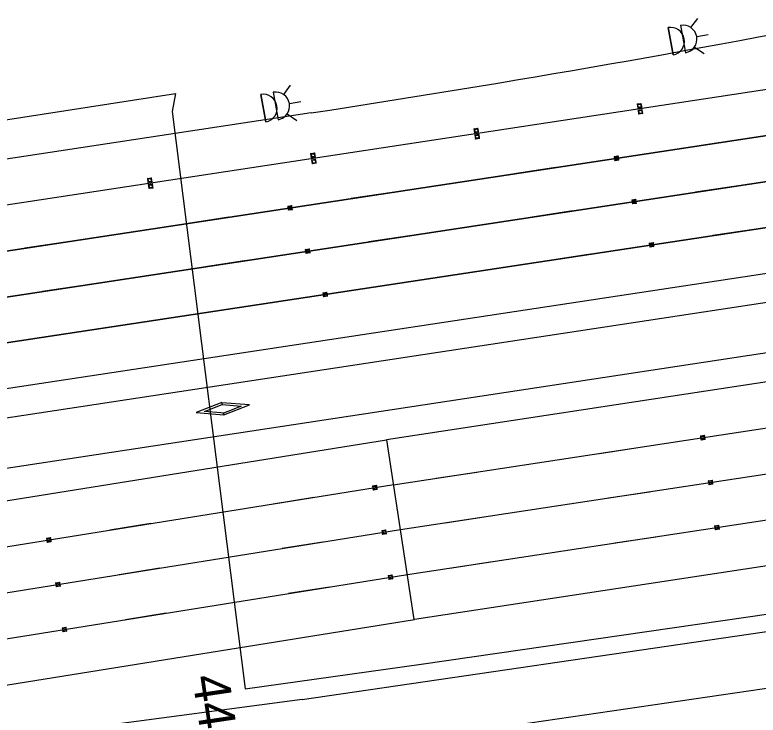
# Model space of a CAD drawing. Extents: x 2471014 to 2497726, y 6959577 to 6980268.
# Drawn here: x 2480648.2 to 2480828.3, y 6967099.5 to 6967269 of the extents above; entities that cross this region are included whole.
import ezdxf

# ---------------------------------------------------------------- set-up
doc = ezdxf.new("R2010")
doc.units = 0
for name, color, linetype in [('1', 7, 'Continuous'), ('13', 7, 'Continuous'), ('15', 7, 'Continuous'), ('18', 7, 'Continuous'), ('23', 7, 'Continuous'), ('25', 7, 'Continuous'), ('5', 7, 'Continuous'), ('C-COMM-IDEN', 7, 'Continuous'), ('PMK_Pav_Mark_Wht_Number', 7, 'Continuous'), ('PMK_Pav_Mark_Wht_Symb', 7, 'Continuous'), ('S-BRDG-BENT', 7, 'Continuous'), ('V7_25', 7, 'Continuous'), ('V7_50', 7, 'Continuous')]:
    doc.layers.add(name, color=color, linetype=linetype)

msp = doc.modelspace()

# ---------------------------------------------------------------- linework, layer by layer
at = {"layer": '1'}
for p, q in [((2480818.71, 6967238.03), (2480808.82, 6967236.53)), ((2480779.16, 6967232.03), (2480769.27, 6967230.53)), ((2480822.95, 6967227.55), (2480813.07, 6967226.05)), ((2480739.61, 6967226.02), (2480729.73, 6967224.52)), ((2480783.41, 6967221.55), (2480773.52, 6967220.04)), ((2480700.07, 6967220.02), (2480690.18, 6967218.52)), ((2480827.2, 6967217.07), (2480817.31, 6967215.57)), ((2480743.86, 6967215.54), (2480733.97, 6967214.04)), ((2480660.52, 6967214.01), (2480650.63, 6967212.51)), ((2480704.31, 6967209.54), (2480694.43, 6967208.03)), ((2480787.65, 6967211.06), (2480777.76, 6967209.56)), ((2480748.1, 6967205.06), (2480738.22, 6967203.56)), ((2480664.77, 6967203.53), (2480654.88, 6967202.03)), ((2480708.56, 6967199.05), (2480698.67, 6967197.55)), ((2480669.01, 6967193.05), (2480659.12, 6967191.55)), ((2480789.81, 6967162.84), (2480799.7, 6967164.34)), ((2480750.27, 6967156.84), (2480760.15, 6967158.34)), ((2480792.04, 6967152.05), (2480801.93, 6967153.56)), ((2480720.63, 6967152.17), (2480710.76, 6967150.59)), ((2480752.5, 6967146.05), (2480762.38, 6967147.55)), ((2480681.14, 6967145.84), (2480671.26, 6967144.25)), ((2480722.86, 6967141.39), (2480712.99, 6967139.81)), ((2480793.59, 6967141.16), (2480803.48, 6967142.67)), ((2480754.05, 6967135.16), (2480763.93, 6967136.66)), ((2480683.37, 6967135.05), (2480673.49, 6967133.47)), ((2480724.41, 6967130.5), (2480714.54, 6967128.91)), ((2480684.91, 6967124.16), (2480675.04, 6967122.58))]:
    msp.add_line(p, q, dxfattribs=at)
at = {"layer": '13'}
for p, q in [((2481763.47, 6967348.11), (2480328.46, 6967130.21)), ((2481593.94, 6967296.07), (2480738.25, 6967166.14)), ((2480338.75, 6967102.06), (2480738.25, 6967166.14))]:
    msp.add_line(p, q, dxfattribs=at)
at = {"layer": '15'}
for p, q in [((2480717.84, 6967103.25), (2481462.38, 6967212.06)), ((2480719.04, 6967089.77), (2481463.87, 6967198.71))]:
    msp.add_line(p, q, dxfattribs=at)
msp.add_lwpolyline([(2480717.84, 6967103.25), (2480607.69, 6967088.69), (2480530.66, 6967079.46)], dxfattribs=at)
at = {"layer": '18'}
for p, q in [((2481764.52, 6967341.19), (2480329.51, 6967123.29)), ((2481592.89, 6967302.99), (2480331.31, 6967111.43)), ((2481600.55, 6967252.57), (2480745.04, 6967122.66)), ((2480719.99, 6967245.29), (2480411.94, 6967198.52))]:
    msp.add_line(p, q, dxfattribs=at)
msp.add_arc((2480242.59, 6970389.25), 3180, 278.63432, 283.91609, dxfattribs=at)
at = {"layer": '23'}
for p, q in [((2480798.96, 6967247.44), (2480799.96, 6967247.59)), ((2480799.15, 6967247.29), (2480798.96, 6967247.44)), ((2480798.96, 6967247.44), (2480799.11, 6967246.44)), ((2480799.23, 6967246.76), (2480799.15, 6967247.29)), ((2480799.96, 6967247.59), (2480799.82, 6967247.39)), ((2480799.82, 6967247.39), (2480799.92, 6967246.72)), ((2480800.07, 6967246.86), (2480799.96, 6967247.59)), ((2480799.11, 6967246.44), (2480799.25, 6967246.62)), ((2480800.11, 6967246.59), (2480799.11, 6967246.44)), ((2480799.18, 6967245.96), (2480800.19, 6967246.11)), ((2480799.38, 6967245.81), (2480799.18, 6967245.96)), ((2480799.18, 6967245.96), (2480799.33, 6967244.95)), ((2480799.25, 6967246.62), (2480799.23, 6967246.76)), ((2480799.46, 6967245.28), (2480799.38, 6967245.81)), ((2480799.92, 6967246.72), (2480800.11, 6967246.59)), ((2480800.19, 6967246.11), (2480800.05, 6967245.91)), ((2480800.05, 6967245.91), (2480800.15, 6967245.24)), ((2480800.11, 6967246.59), (2480800.07, 6967246.86)), ((2480800.3, 6967245.37), (2480800.19, 6967246.11)), ((2480800.34, 6967245.11), (2480800.3, 6967245.37)), ((2480799.33, 6967244.95), (2480799.48, 6967245.14)), ((2480800.34, 6967245.11), (2480799.33, 6967244.95)), ((2480799.48, 6967245.14), (2480799.46, 6967245.28)), ((2480800.15, 6967245.24), (2480800.34, 6967245.11)), ((2480759.41, 6967241.44), (2480760.41, 6967241.59)), ((2480759.61, 6967241.29), (2480759.41, 6967241.44)), ((2480759.41, 6967241.44), (2480759.56, 6967240.43)), ((2480759.56, 6967240.43), (2480759.71, 6967240.62)), ((2480760.57, 6967240.59), (2480759.56, 6967240.43)), ((2480759.69, 6967240.76), (2480759.61, 6967241.29)), ((2480759.64, 6967239.95), (2480760.64, 6967240.1)), ((2480759.83, 6967239.8), (2480759.64, 6967239.95)), ((2480759.64, 6967239.95), (2480759.79, 6967238.95)), ((2480759.71, 6967240.62), (2480759.69, 6967240.76)), ((2480760.41, 6967241.59), (2480760.28, 6967241.39)), ((2480760.28, 6967241.39), (2480760.38, 6967240.72)), ((2480760.38, 6967240.72), (2480760.57, 6967240.59)), ((2480760.53, 6967240.85), (2480760.41, 6967241.59)), ((2480760.64, 6967240.1), (2480760.5, 6967239.9)), ((2480760.57, 6967240.59), (2480760.53, 6967240.85)), ((2480760.75, 6967239.37), (2480760.64, 6967240.1)), ((2480759.79, 6967238.95), (2480759.93, 6967239.13)), ((2480760.79, 6967239.1), (2480759.79, 6967238.95)), ((2480759.91, 6967239.27), (2480759.83, 6967239.8)), ((2480759.93, 6967239.13), (2480759.91, 6967239.27)), ((2480760.5, 6967239.9), (2480760.6, 6967239.23)), ((2480760.6, 6967239.23), (2480760.79, 6967239.1)), ((2480760.79, 6967239.1), (2480760.75, 6967239.37)), ((2480719.87, 6967235.43), (2480720.87, 6967235.58)), ((2480720.06, 6967235.28), (2480719.87, 6967235.43)), ((2480719.87, 6967235.43), (2480720.02, 6967234.43)), ((2480720.02, 6967234.43), (2480720.16, 6967234.61)), ((2480721.02, 6967234.58), (2480720.02, 6967234.43)), ((2480720.14, 6967234.75), (2480720.06, 6967235.28)), ((2480720.16, 6967234.61), (2480720.14, 6967234.75)), ((2480720.87, 6967235.58), (2480720.73, 6967235.38)), ((2480720.73, 6967235.38), (2480720.83, 6967234.71)), ((2480720.83, 6967234.71), (2480721.02, 6967234.58)), ((2480720.98, 6967234.85), (2480720.87, 6967235.58)), ((2480721.02, 6967234.58), (2480720.98, 6967234.85)), ((2480793.41, 6967234.71), (2480794.41, 6967234.87)), ((2480793.61, 6967234.56), (2480793.41, 6967234.71)), ((2480793.41, 6967234.71), (2480793.56, 6967233.71)), ((2480793.69, 6967234.03), (2480793.61, 6967234.56)), ((2480794.41, 6967234.87), (2480794.28, 6967234.66)), ((2480794.28, 6967234.66), (2480794.38, 6967234)), ((2480794.53, 6967234.13), (2480794.41, 6967234.87)), ((2480720.09, 6967233.95), (2480721.09, 6967234.1)), ((2480720.28, 6967233.8), (2480720.09, 6967233.95)), ((2480720.09, 6967233.95), (2480720.24, 6967232.94)), ((2480720.24, 6967232.94), (2480720.39, 6967233.13)), ((2480721.25, 6967233.1), (2480720.24, 6967232.94)), ((2480720.36, 6967233.27), (2480720.28, 6967233.8)), ((2480720.39, 6967233.13), (2480720.36, 6967233.27)), ((2480721.09, 6967234.1), (2480720.95, 6967233.9)), ((2480720.95, 6967233.9), (2480721.06, 6967233.23)), ((2480721.06, 6967233.23), (2480721.25, 6967233.1)), ((2480721.21, 6967233.36), (2480721.09, 6967234.1)), ((2480721.25, 6967233.1), (2480721.21, 6967233.36)), ((2480793.56, 6967233.71), (2480793.71, 6967233.89)), ((2480794.57, 6967233.86), (2480793.56, 6967233.71)), ((2480793.71, 6967233.89), (2480793.69, 6967234.03)), ((2480794.38, 6967234), (2480794.57, 6967233.86)), ((2480794.57, 6967233.86), (2480794.53, 6967234.13)), ((2480680.32, 6967229.43), (2480681.32, 6967229.58)), ((2480680.51, 6967229.28), (2480680.32, 6967229.43)), ((2480680.32, 6967229.43), (2480680.47, 6967228.42)), ((2480680.59, 6967228.75), (2480680.51, 6967229.28)), ((2480681.32, 6967229.58), (2480681.18, 6967229.38)), ((2480681.18, 6967229.38), (2480681.28, 6967228.71)), ((2480681.43, 6967228.84), (2480681.32, 6967229.58)), ((2480680.47, 6967228.42), (2480680.61, 6967228.61)), ((2480681.47, 6967228.58), (2480680.47, 6967228.42)), ((2480680.54, 6967227.94), (2480681.55, 6967228.09)), ((2480680.74, 6967227.79), (2480680.54, 6967227.94)), ((2480680.54, 6967227.94), (2480680.69, 6967226.94)), ((2480680.61, 6967228.61), (2480680.59, 6967228.75)), ((2480680.82, 6967227.26), (2480680.74, 6967227.79)), ((2480681.28, 6967228.71), (2480681.47, 6967228.58)), ((2480681.55, 6967228.09), (2480681.41, 6967227.89)), ((2480681.41, 6967227.89), (2480681.51, 6967227.22)), ((2480681.47, 6967228.58), (2480681.43, 6967228.84)), ((2480681.66, 6967227.36), (2480681.55, 6967228.09)), ((2480681.7, 6967227.09), (2480681.66, 6967227.36)), ((2480680.69, 6967226.94), (2480680.84, 6967227.12)), ((2480681.7, 6967227.09), (2480680.69, 6967226.94)), ((2480680.84, 6967227.12), (2480680.82, 6967227.26)), ((2480681.51, 6967227.22), (2480681.7, 6967227.09)), ((2480797.66, 6967224.23), (2480798.66, 6967224.38)), ((2480797.85, 6967224.08), (2480797.66, 6967224.23)), ((2480797.66, 6967224.23), (2480797.81, 6967223.23)), ((2480797.93, 6967223.55), (2480797.85, 6967224.08)), ((2480798.66, 6967224.38), (2480798.52, 6967224.18)), ((2480798.52, 6967224.18), (2480798.62, 6967223.51)), ((2480798.77, 6967223.65), (2480798.66, 6967224.38)), ((2480714.32, 6967222.7), (2480715.32, 6967222.85)), ((2480714.51, 6967222.55), (2480714.32, 6967222.7)), ((2480714.32, 6967222.7), (2480714.47, 6967221.7)), ((2480714.59, 6967222.02), (2480714.51, 6967222.55)), ((2480714.62, 6967221.88), (2480714.59, 6967222.02)), ((2480715.32, 6967222.85), (2480715.18, 6967222.65)), ((2480715.18, 6967222.65), (2480715.28, 6967221.99)), ((2480715.28, 6967221.99), (2480715.47, 6967221.85)), ((2480715.43, 6967222.12), (2480715.32, 6967222.85)), ((2480715.47, 6967221.85), (2480715.43, 6967222.12)), ((2480797.81, 6967223.23), (2480797.95, 6967223.41)), ((2480798.81, 6967223.38), (2480797.81, 6967223.23)), ((2480797.95, 6967223.41), (2480797.93, 6967223.55)), ((2480798.62, 6967223.51), (2480798.81, 6967223.38)), ((2480798.81, 6967223.38), (2480798.77, 6967223.65)), ((2480714.47, 6967221.7), (2480714.62, 6967221.88)), ((2480715.47, 6967221.85), (2480714.47, 6967221.7)), ((2480801.9, 6967213.75), (2480802.9, 6967213.9)), ((2480802.1, 6967213.6), (2480801.9, 6967213.75)), ((2480801.9, 6967213.75), (2480802.05, 6967212.75)), ((2480802.05, 6967212.75), (2480802.2, 6967212.93)), ((2480802.18, 6967213.07), (2480802.1, 6967213.6)), ((2480802.2, 6967212.93), (2480802.18, 6967213.07)), ((2480802.9, 6967213.9), (2480802.76, 6967213.7)), ((2480802.76, 6967213.7), (2480802.87, 6967213.03)), ((2480802.87, 6967213.03), (2480803.05, 6967212.9)), ((2480803.01, 6967213.17), (2480802.9, 6967213.9)), ((2480803.05, 6967212.9), (2480803.01, 6967213.17)), ((2480718.56, 6967212.22), (2480719.57, 6967212.37)), ((2480718.76, 6967212.07), (2480718.56, 6967212.22)), ((2480718.56, 6967212.22), (2480718.71, 6967211.22)), ((2480718.71, 6967211.22), (2480718.86, 6967211.4)), ((2480719.72, 6967211.37), (2480718.71, 6967211.22)), ((2480718.84, 6967211.54), (2480718.76, 6967212.07)), ((2480718.86, 6967211.4), (2480718.84, 6967211.54)), ((2480719.57, 6967212.37), (2480719.43, 6967212.17)), ((2480719.43, 6967212.17), (2480719.53, 6967211.5)), ((2480719.53, 6967211.5), (2480719.72, 6967211.37)), ((2480719.68, 6967211.64), (2480719.57, 6967212.37)), ((2480719.72, 6967211.37), (2480719.68, 6967211.64)), ((2480803.05, 6967212.9), (2480802.05, 6967212.75)), ((2480722.81, 6967201.74), (2480723.81, 6967201.89)), ((2480723, 6967201.59), (2480722.81, 6967201.74)), ((2480722.81, 6967201.74), (2480722.96, 6967200.74)), ((2480722.96, 6967200.74), (2480723.1, 6967200.92)), ((2480723.96, 6967200.89), (2480722.96, 6967200.74)), ((2480723.08, 6967201.06), (2480723, 6967201.59)), ((2480723.1, 6967200.92), (2480723.08, 6967201.06)), ((2480723.81, 6967201.89), (2480723.67, 6967201.69)), ((2480723.67, 6967201.69), (2480723.77, 6967201.02)), ((2480723.77, 6967201.02), (2480723.96, 6967200.89)), ((2480723.92, 6967201.16), (2480723.81, 6967201.89)), ((2480723.96, 6967200.89), (2480723.92, 6967201.16)), ((2480814.31, 6967167.06), (2480815.31, 6967167.22)), ((2480814.49, 6967166.93), (2480814.31, 6967167.06)), ((2480814.31, 6967167.06), (2480814.35, 6967166.8)), ((2480814.35, 6967166.8), (2480814.46, 6967166.06)), ((2480814.46, 6967166.06), (2480814.6, 6967166.26)), ((2480815.46, 6967166.21), (2480814.46, 6967166.06)), ((2480814.6, 6967166.26), (2480814.49, 6967166.93)), ((2480815.31, 6967167.22), (2480815.16, 6967167.03)), ((2480815.16, 6967167.03), (2480815.18, 6967166.89)), ((2480815.18, 6967166.89), (2480815.26, 6967166.36)), ((2480815.26, 6967166.36), (2480815.46, 6967166.21)), ((2480815.46, 6967166.21), (2480815.31, 6967167.22)), ((2480816.19, 6967156.22), (2480817.19, 6967156.38)), ((2480816.38, 6967156.09), (2480816.19, 6967156.22)), ((2480816.19, 6967156.22), (2480816.23, 6967155.96)), ((2480816.23, 6967155.96), (2480816.34, 6967155.22)), ((2480816.34, 6967155.22), (2480816.48, 6967155.42)), ((2480817.34, 6967155.37), (2480816.34, 6967155.22)), ((2480816.48, 6967155.42), (2480816.38, 6967156.09)), ((2480817.19, 6967156.38), (2480817.04, 6967156.19)), ((2480817.04, 6967156.19), (2480817.07, 6967156.05)), ((2480817.07, 6967156.05), (2480817.15, 6967155.52)), ((2480817.15, 6967155.52), (2480817.34, 6967155.37)), ((2480817.34, 6967155.37), (2480817.19, 6967156.38)), ((2480734.86, 6967154.98), (2480735.86, 6967155.14)), ((2480735.06, 6967154.83), (2480734.86, 6967154.98)), ((2480734.86, 6967154.98), (2480735.02, 6967153.98)), ((2480735.02, 6967153.98), (2480735.16, 6967154.16)), ((2480736.02, 6967154.14), (2480735.02, 6967153.98)), ((2480735.14, 6967154.3), (2480735.06, 6967154.83)), ((2480735.16, 6967154.16), (2480735.14, 6967154.3)), ((2480735.86, 6967155.14), (2480735.72, 6967154.94)), ((2480735.72, 6967154.94), (2480735.83, 6967154.27)), ((2480735.83, 6967154.27), (2480736.02, 6967154.14)), ((2480735.98, 6967154.4), (2480735.86, 6967155.14)), ((2480736.02, 6967154.14), (2480735.98, 6967154.4)), ((2480817.73, 6967145.33), (2480818.74, 6967145.48)), ((2480817.92, 6967145.2), (2480817.73, 6967145.33)), ((2480817.73, 6967145.33), (2480817.77, 6967145.07)), ((2480817.77, 6967145.07), (2480817.89, 6967144.33)), ((2480817.89, 6967144.33), (2480818.02, 6967144.53)), ((2480818.02, 6967144.53), (2480817.92, 6967145.2)), ((2480818.74, 6967145.48), (2480818.59, 6967145.3)), ((2480818.59, 6967145.3), (2480818.61, 6967145.16)), ((2480818.61, 6967145.16), (2480818.69, 6967144.63)), ((2480818.69, 6967144.63), (2480818.89, 6967144.48)), ((2480818.89, 6967144.48), (2480818.74, 6967145.48)), ((2480737.09, 6967144.19), (2480738.09, 6967144.35)), ((2480737.29, 6967144.05), (2480737.09, 6967144.19)), ((2480737.09, 6967144.19), (2480737.25, 6967143.19)), ((2480737.25, 6967143.19), (2480737.39, 6967143.38)), ((2480738.25, 6967143.35), (2480737.25, 6967143.19)), ((2480737.37, 6967143.52), (2480737.29, 6967144.05)), ((2480737.39, 6967143.38), (2480737.37, 6967143.52)), ((2480738.09, 6967144.35), (2480737.95, 6967144.15)), ((2480737.95, 6967144.15), (2480738.06, 6967143.49)), ((2480738.06, 6967143.49), (2480738.25, 6967143.35)), ((2480738.21, 6967143.62), (2480738.09, 6967144.35)), ((2480738.25, 6967143.35), (2480738.21, 6967143.62)), ((2480818.89, 6967144.48), (2480817.89, 6967144.33)), ((2480655.87, 6967142.31), (2480656.87, 6967142.47)), ((2480656.06, 6967142.16), (2480655.87, 6967142.31)), ((2480655.87, 6967142.31), (2480656.03, 6967141.31)), ((2480656.03, 6967141.31), (2480656.17, 6967141.49)), ((2480657.03, 6967141.47), (2480656.03, 6967141.31)), ((2480656.15, 6967141.63), (2480656.06, 6967142.16)), ((2480656.17, 6967141.49), (2480656.15, 6967141.63)), ((2480656.87, 6967142.47), (2480656.73, 6967142.27)), ((2480656.73, 6967142.27), (2480656.84, 6967141.6)), ((2480656.84, 6967141.6), (2480657.03, 6967141.47)), ((2480656.99, 6967141.73), (2480656.87, 6967142.47)), ((2480657.03, 6967141.47), (2480656.99, 6967141.73)), ((2480738.64, 6967133.3), (2480739.64, 6967133.46)), ((2480738.83, 6967133.15), (2480738.64, 6967133.3)), ((2480738.64, 6967133.3), (2480738.8, 6967132.3)), ((2480738.8, 6967132.3), (2480738.94, 6967132.49)), ((2480739.8, 6967132.46), (2480738.8, 6967132.3)), ((2480738.92, 6967132.63), (2480738.83, 6967133.15)), ((2480738.94, 6967132.49), (2480738.92, 6967132.63)), ((2480739.64, 6967133.46), (2480739.5, 6967133.26)), ((2480739.5, 6967133.26), (2480739.61, 6967132.59)), ((2480739.61, 6967132.59), (2480739.8, 6967132.46)), ((2480739.76, 6967132.73), (2480739.64, 6967133.46)), ((2480739.8, 6967132.46), (2480739.76, 6967132.73)), ((2480658.1, 6967131.52), (2480659.1, 6967131.68)), ((2480658.3, 6967131.38), (2480658.1, 6967131.52)), ((2480658.1, 6967131.52), (2480658.26, 6967130.52)), ((2480658.26, 6967130.52), (2480658.4, 6967130.71)), ((2480659.26, 6967130.69), (2480658.26, 6967130.52)), ((2480658.38, 6967130.85), (2480658.3, 6967131.38)), ((2480658.4, 6967130.71), (2480658.38, 6967130.85)), ((2480659.1, 6967131.68), (2480658.96, 6967131.48)), ((2480658.96, 6967131.48), (2480659.07, 6967130.82)), ((2480659.07, 6967130.82), (2480659.26, 6967130.69)), ((2480659.22, 6967130.95), (2480659.1, 6967131.68)), ((2480659.26, 6967130.69), (2480659.22, 6967130.95)), ((2480659.65, 6967120.63), (2480660.65, 6967120.79)), ((2480659.84, 6967120.48), (2480659.65, 6967120.63)), ((2480659.65, 6967120.63), (2480659.81, 6967119.63)), ((2480659.81, 6967119.63), (2480659.95, 6967119.82)), ((2480660.81, 6967119.79), (2480659.81, 6967119.63)), ((2480659.93, 6967119.96), (2480659.84, 6967120.48)), ((2480659.95, 6967119.82), (2480659.93, 6967119.96)), ((2480660.65, 6967120.79), (2480660.51, 6967120.59)), ((2480660.51, 6967120.59), (2480660.62, 6967119.92)), ((2480660.62, 6967119.92), (2480660.81, 6967119.79)), ((2480660.77, 6967120.06), (2480660.65, 6967120.79)), ((2480660.81, 6967119.79), (2480660.77, 6967120.06))]:
    msp.add_line(p, q, dxfattribs=at)
for points in [[(2480799.92, 6967246.72), (2480799.25, 6967246.62), (2480799.15, 6967247.29), (2480799.82, 6967247.39)], [(2480800.15, 6967245.24), (2480799.48, 6967245.14), (2480799.38, 6967245.81), (2480800.05, 6967245.91)], [(2480760.38, 6967240.72), (2480759.71, 6967240.62), (2480759.61, 6967241.29), (2480760.28, 6967241.39)], [(2480760.6, 6967239.23), (2480759.93, 6967239.13), (2480759.83, 6967239.8), (2480760.5, 6967239.9)], [(2480720.83, 6967234.71), (2480720.16, 6967234.61), (2480720.06, 6967235.28), (2480720.73, 6967235.38)], [(2480794.38, 6967234), (2480793.71, 6967233.89), (2480793.61, 6967234.56), (2480794.28, 6967234.66)], [(2480721.06, 6967233.23), (2480720.39, 6967233.13), (2480720.28, 6967233.8), (2480720.95, 6967233.9)], [(2480681.28, 6967228.71), (2480680.61, 6967228.61), (2480680.51, 6967229.28), (2480681.18, 6967229.38)], [(2480681.51, 6967227.22), (2480680.84, 6967227.12), (2480680.74, 6967227.79), (2480681.41, 6967227.89)], [(2480798.62, 6967223.51), (2480797.95, 6967223.41), (2480797.85, 6967224.08), (2480798.52, 6967224.18)], [(2480715.28, 6967221.99), (2480714.62, 6967221.88), (2480714.51, 6967222.55), (2480715.18, 6967222.65)], [(2480802.87, 6967213.03), (2480802.2, 6967212.93), (2480802.1, 6967213.6), (2480802.76, 6967213.7)], [(2480719.53, 6967211.5), (2480718.86, 6967211.4), (2480718.76, 6967212.07), (2480719.43, 6967212.17)], [(2480723.77, 6967201.02), (2480723.1, 6967200.92), (2480723, 6967201.59), (2480723.67, 6967201.69)], [(2480814.49, 6967166.93), (2480815.16, 6967167.03), (2480815.26, 6967166.36), (2480814.6, 6967166.26)], [(2480816.38, 6967156.09), (2480817.04, 6967156.19), (2480817.15, 6967155.52), (2480816.48, 6967155.42)], [(2480735.83, 6967154.27), (2480735.16, 6967154.16), (2480735.06, 6967154.83), (2480735.72, 6967154.94)], [(2480817.92, 6967145.2), (2480818.59, 6967145.3), (2480818.69, 6967144.63), (2480818.02, 6967144.53)], [(2480738.06, 6967143.49), (2480737.39, 6967143.38), (2480737.29, 6967144.05), (2480737.95, 6967144.15)], [(2480656.84, 6967141.6), (2480656.17, 6967141.49), (2480656.06, 6967142.16), (2480656.73, 6967142.27)], [(2480739.61, 6967132.59), (2480738.94, 6967132.49), (2480738.83, 6967133.15), (2480739.5, 6967133.26)], [(2480659.07, 6967130.82), (2480658.4, 6967130.71), (2480658.3, 6967131.38), (2480658.96, 6967131.48)], [(2480660.62, 6967119.92), (2480659.95, 6967119.82), (2480659.84, 6967120.48), (2480660.51, 6967120.59)]]:
    msp.add_lwpolyline(points, close=True, dxfattribs=at)
at = {"layer": '25'}
msp.add_line((2480345.5, 6967058.58), (2480745.04, 6967122.66), dxfattribs=at)
at = {"layer": '5'}
msp.add_line((2480858.48, 6967255.2), (2480561.88, 6967210.16), dxfattribs=at)
msp.add_arc((2479474.04, 6969335.88), 8460, 6.37617, 6.37617, dxfattribs=at)
at = {"layer": 'C-COMM-IDEN'}
for p, q in [((2480812.01, 6967265.93), (2480813.7, 6967268.17)), ((2480807.67, 6967259.3), (2480806.48, 6967265.94)), ((2480806.48, 6967265.94), (2480807.67, 6967259.3)), ((2480809.48, 6967266.48), (2480810.67, 6967259.84)), ((2480813.4, 6967263.75), (2480816.17, 6967264.25)), ((2480812.85, 6967261.23), (2480815.18, 6967259.66)), ((2480713.34, 6967249.72), (2480715.03, 6967251.96)), ((2480709, 6967243.09), (2480707.81, 6967249.73)), ((2480707.81, 6967249.73), (2480709, 6967243.09)), ((2480710.81, 6967250.27), (2480712, 6967243.63)), ((2480714.73, 6967247.54), (2480717.5, 6967248.04)), ((2480714.18, 6967245.02), (2480716.51, 6967243.45))]:
    msp.add_line(p, q, dxfattribs=at)
for centre in [(2480807.07, 6967262.62), (2480810.08, 6967263.16), (2480708.4, 6967246.41), (2480711.41, 6967246.95)]:
    msp.add_arc(centre, 3.37, 280.1538, 100.1538, dxfattribs=at)
at = {"layer": 'PMK_Pav_Mark_Wht_Symb'}
for p, q in [((2480698.4, 6967175.13), (2480692.18, 6967172.71)), ((2480698.46, 6967174.67), (2480698.4, 6967175.13)), ((2480705.04, 6967174.57), (2480698.4, 6967175.12)), ((2480698.4, 6967175.12), (2480698.46, 6967174.67)), ((2480694.17, 6967173), (2480698.46, 6967174.67)), ((2480698.46, 6967174.67), (2480703.05, 6967174.28)), ((2480700.86, 6967173.43), (2480698.76, 6967172.62)), ((2480698.82, 6967172.16), (2480705.04, 6967174.57)), ((2480703.05, 6967174.28), (2480700.86, 6967173.43)), ((2480692.18, 6967172.71), (2480698.82, 6967172.16)), ((2480698.1, 6967172.67), (2480694.17, 6967173)), ((2480698.76, 6967172.62), (2480698.1, 6967172.67)), ((2480698.76, 6967172.62), (2480698.82, 6967172.16)), ((2480698.82, 6967172.16), (2480698.76, 6967172.62))]:
    msp.add_line(p, q, dxfattribs=at)
at = {"layer": 'S-BRDG-BENT'}
for p, q in [((2481758.52, 6967380.74), (2480323.5, 6967162.84)), ((2481760.17, 6967369.87), (2480325.16, 6967151.96)), ((2481761.82, 6967358.99), (2480326.81, 6967141.09)), ((2481763.47, 6967348.11), (2480328.46, 6967130.21)), ((2480858.48, 6967255.2), (2480321.85, 6967173.71)), ((2480719.99, 6967245.29), (2480320.2, 6967184.59)), ((2480738.25, 6967166.14), (2480744.86, 6967122.64)), ((2480340.44, 6967091.19), (2480739.99, 6967155.28)), ((2480342.13, 6967080.32), (2480741.64, 6967144.4)), ((2480343.82, 6967069.45), (2480743.34, 6967133.53))]:
    msp.add_line(p, q, dxfattribs=at)
msp.add_arc((2480242.59, 6970389.25), 3180, 278.63432, 283.91609, dxfattribs=at)
at = {"layer": 'V7_25'}
for p, q in [((2480323.5, 6967162.84), (2481758.52, 6967380.74)), ((2480325.16, 6967151.96), (2481760.17, 6967369.87)), ((2480326.81, 6967141.09), (2481761.82, 6967358.99)), ((2480739.9, 6967155.26), (2481595.59, 6967285.2)), ((2480741.64, 6967144.4), (2481597.25, 6967274.32)), ((2480743.34, 6967133.53), (2481598.9, 6967263.45))]:
    msp.add_line(p, q, dxfattribs=at)
at = {"layer": 'V7_50'}
msp.add_lwpolyline([(2481147.36, 6967423.75), (2480793.84, 6967370.67), (2480555.68, 6967367.58), (2480539.68, 6967347.67), (2480461.84, 6967335.98), (2480420.21, 6967349.5), (2480410.08, 6967345.94), (2480421.83, 6967319.12), (2480415.63, 6967313.77), (2480429.34, 6967302.76), (2480444.99, 6967295.17), (2480459.46, 6967292.51), (2480472.21, 6967292.15), (2480480.9, 6967234.3), (2480473.12, 6967225.44), (2480468.38, 6967217.08), (2480469.85, 6967216.31), (2480687.16, 6967249.95), (2480686.35, 6967245.6), (2480704.04, 6967105.84), (2480746.63, 6967111.84), (2480904.51, 6967134.66)], dxfattribs=at)

# ---------------------------------------------------------------- texts
at = {"layer": 'PMK_Pav_Mark_Wht_Number'}
msp.add_text('44', height=8.9, rotation=278.4682, dxfattribs=at).set_placement((2480691.15, 6967108.74))

doc.saveas('drawing.dxf')
